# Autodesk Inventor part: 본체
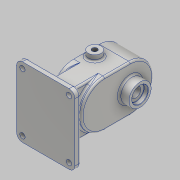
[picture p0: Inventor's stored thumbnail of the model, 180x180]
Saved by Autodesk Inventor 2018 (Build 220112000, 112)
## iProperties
Created: 2020-09
Part Number: 본체
Material: 알루미늄 6061
Document SubType Name: Modeling
Designer: home
Density: 2.7 g/cm^3
Appearance: 알루미늄 - 평지
Mass: 1438.79 g
Surface Area: 787.723 cm^2
Volume: 532.885 cm^3
Author: home
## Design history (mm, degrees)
sketch "스케치1"
  geometry: L1 (50, 60)-(-50, 60); L2 (-50, 60)-(-50, -60); L3 (-50, -60)-(50, -60); L4 (50, -60)-(50, 60); L5 (50, 60)-(-50, -60); 2 further points
  constraints: 10 end point, 2 parallel, 1 coincident, 1 horizontal, 1 midpoint, 1 perpendicular
  dimensions: "d0" = 120 distance of L3.end L1.start; "d1" = 100 distance of L1.start L1.end
extrude "돌출1" new body sketch "스케치1" distance "d3" = 10; taper "d4" = 0 deg
node "작업 평면1"
sketch "스케치3"
  geometry: L1 (120, 0)-(0, 0) reference; L2 (20, 112)-(20, 68); L3 (100, 112)-(100, 68); A1 r 40 centre (60, 112) between (100, 112) and (20, 112); A2 r 40 centre (60, 68) between (20, 68) and (100, 68); 1 further point
  constraints: 4 end point, 4 point on circle, 2 centre point, 2 tangent, 2 vertical alignment, 1 parallel, 1 vertical
  dimensions: "d10" = 80 diameter of A1; "d11" = 80 diameter of A2; "d12" = 44 distance of A2.centre A1.centre; "d13" = 112 distance from line of A1.centre L1
extrude "돌출2" join sketch "스케치3" distance "d14" = 53; taper "d15" = 0 deg
sketch "스케치4"
  geometry: L1 (-84, 112)-(-84, 68); L2 (-36, 112)-(-36, 68); A1 r 40 centre (-60, 112) between (-20, 112) and (-100, 112) reference; A2 r 24 centre (-60, 112) between (-36, 112) and (-84, 112); A3 r 24 centre (-60, 68) between (-84, 68) and (-36, 68); A4 r 40 centre (-60, 68) between (-100, 68) and (-20, 68) reference; 1 further point
  constraints: 4 end point, 4 point on circle, 2 centre point, 2 tangent, 1 coincident, 1 concentric, 1 parallel, 1 vertical
  dimensions: "d16" = 48 diameter of A2; "d17" = 48 diameter of A3
extrude "돌출3" cut sketch "스케치4" distance "d18" = 29; taper "d19" = 0 deg
sketch "스케치5"
  geometry: A1 r 24 centre (-60, 68) between (-84, 68) and (-36, 68) reference; 2 further points
  constraints: 1 vertical alignment
  dimensions: "d20" = 44 distance of point (-60, 112) A1.centre
hole "구멍1" sketch "스케치5" at (-60, 112) diameter "d21" = 17; stored, may be unused: countersink angle "d25" = 90 deg, drill point angle "d27" = 118 deg; dims "d22" = 6, "d23" = 25, "d24" = 15, "d26" = 8
sketch "스케치8"
  geometry: C1 r 12.5 at (-60, 68); A1 r 24 centre (-60, 68) between (-84, 68) and (-36, 68) reference; 1 further point
  constraints: 1 centre point, 1 concentric
  dimensions: "d39" = 25 diameter of C1
extrude "돌출6" cut sketch "스케치8" distance "d40" = 15; taper "d41" = 0 deg
sketch "스케치9"
  geometry: L1 (-83, -68)-(17, -68) reference; L2 (-53, 0)-(-53, 44) reference; C1 r 11 at (-39, 22); 1 further point
  constraints: 1 centre point
  dimensions: "d42" = 22 diameter of C1; "d43" = 90 distance from line of C1.centre L1; "d44" = 14 distance from line of C1.centre L2
extrude "돌출7" join sketch "스케치9" distance "d45" = 10; taper "d46" = 0 deg
fillet "모깎기2" dims "d56" = 3
sketch "스케치11"
  geometry: L1 (53, 44)-(53, 0) reference; L2 (-17, -68)-(83, -68) reference; C1 r 11 at (39, 22); 1 further point
  constraints: 1 centre point
  dimensions: "d57" = 22 diameter of C1; "d58" = 14 distance from line of C1.centre L1; "d59" = 90 distance from line of L2 C1.centre
extrude "돌출8" join sketch "스케치11" distance "d60" = 10; taper "d61" = 0 deg
sketch "스케치12"
  geometry: L1 (14, 22)-(14, -22) reference; L2 (-56, -90)-(44, -90) reference; 2 further points
  dimensions: "d62" = 14 distance from line of L1 point (0, 0); "d63" = 90 distance from line of L2 point (0, 0)
hole "구멍3" sketch "스케치12" at (0, 0) diameter "d64" = 8.917; stored, may be unused: countersink angle "d68" = 90 deg, drill point angle "d70" = 118 deg; dims "d65" = 20, "d66" = 25, "d67" = 15, "d69" = 25.1
fillet "모깎기3" dims "d71" = 3
sketch "스케치13"
  geometry: C1 r 8.5 at (-60, 112) reference; A1 r 31 centre (-60, 112) between (-60, 143) and (-29, 112); 2 further points
  constraints: 3 point on circle, 2 horizontal alignment, 1 centre point, 1 coincident, 1 vertical alignment
  dimensions: "d72" = 62 diameter of A1
hole "구멍4" sketch "스케치13" at (-60, 143), (-91, 112), (-29, 112) diameter "d73" = 4.134; stored, may be unused: countersink angle "d77" = 90 deg, drill point angle "d79" = 118 deg; dims "d74" = 10, "d75" = 25, "d76" = 15, "d78" = 12
node "작업 평면2"
node "작업 평면3"
node "작업 평면4"
sketch "스케치14"
  geometry: L1 (100, 68)-(100, 10); L2 (0, 10)-(120, 10) reference; L3 (20, 68)-(20, 10); L4 (100, 10)-(20, 10); A1 r 40 centre (60, 68) between (20, 68) and (100, 68) reference; A2 r 40 centre (60, 68) between (20, 68) and (100, 68); 2 further points
  constraints: 6 end point, 3 point on circle, 2 point on line, 1 centre point, 1 coincident, 1 collinear, 1 parallel, 1 tangent, 1 vertical
extrude "돌출9" join sketch "스케치14" distance "d86" = 37; taper "d87" = 0 deg
fillet "모깎기4" dims "d88" = 3
fillet "모깎기5" dims "d89" = 10
sketch "스케치15"
  geometry: A1 r 10 centre (-40, 50) between (-40, 60) and (-50, 50) reference; A2 r 10 centre (40, 50) between (50, 50) and (40, 60) reference; A3 r 10 centre (40, -50) between (40, -60) and (50, -50) reference; A4 r 10 centre (-40, -50) between (-50, -50) and (-40, -60) reference; 1 further point
hole "구멍5" sketch "스케치15" at (-40, 50), (40, 50), (40, -50), (-40, -50) diameter "d90" = 9; stored, may be unused: countersink angle "d94" = 90 deg, drill point angle "d96" = 118 deg; dims "d91" = 10, "d92" = 25, "d93" = 15, "d95" = 12
fillet "모깎기6" dims "d97" = 3
fillet "모깎기7" dims "d98" = 3
fillet "모깎기8" dims "d99" = 3
chamfer "모따기2" distance "d100" = 1; stored, may be unused: second distance "d101" = 2, angle "d102" = 30 deg
sketch "스케치17"
  geometry: L1 (40, 60)-(-40, 60) reference; L2 (-50, 50)-(-50, -50) reference; 2 further points
  constraints: 1 other
  dimensions: "d103" = 60 distance from line of L1 point (-38, 0); "d104" = 12 distance from line of point (-38, 0) L2
feature "엠보싱1" sketch "스케치17" dims "d105" = 0.5, "d106" = 0
sketch "스케치18"
  geometry: C1 r 8.5 at (60, 112) reference; C2 r 19 at (60, 112); 1 further point
  constraints: 1 centre point, 1 coincident
  dimensions: "d116" = 38 diameter of C2
extrude "돌출10" join sketch "스케치18" distance "d117" = 17; taper "d118" = 0 deg
sketch "스케치19"
  geometry: C1 r 14 at (0, 0); C2 r 19 at (0, 0) reference; 1 further point
  constraints: 1 centre point, 1 concentric
  dimensions: "d119" = 28 diameter of C1
extrude "돌출11" cut sketch "스케치19" distance "d120" = 7.3; taper "d121" = 0 deg
chamfer "모따기6" distance "d122" = 0.7; stored, may be unused: second distance "d123" = 2, angle "d124" = 30 deg
fillet "모깎기9" dims "d125" = 0.5
fillet "모깎기10" dims "d126" = 3
node "솔리드1"
mirror "미러1"
other parameters: "d9" = -17, "d81" = -25
